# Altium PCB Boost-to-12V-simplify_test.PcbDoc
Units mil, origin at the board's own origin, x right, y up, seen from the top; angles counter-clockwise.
Board outline 618 x 524 mil, 2 copper layers (Top Layer, Bottom Layer); 13 components, 7 nets, 29 pads, 14 vias.
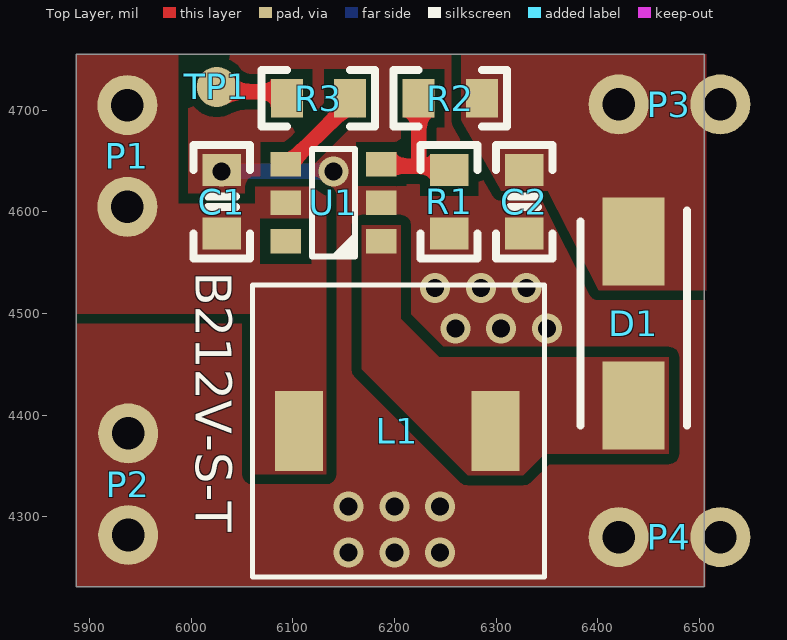
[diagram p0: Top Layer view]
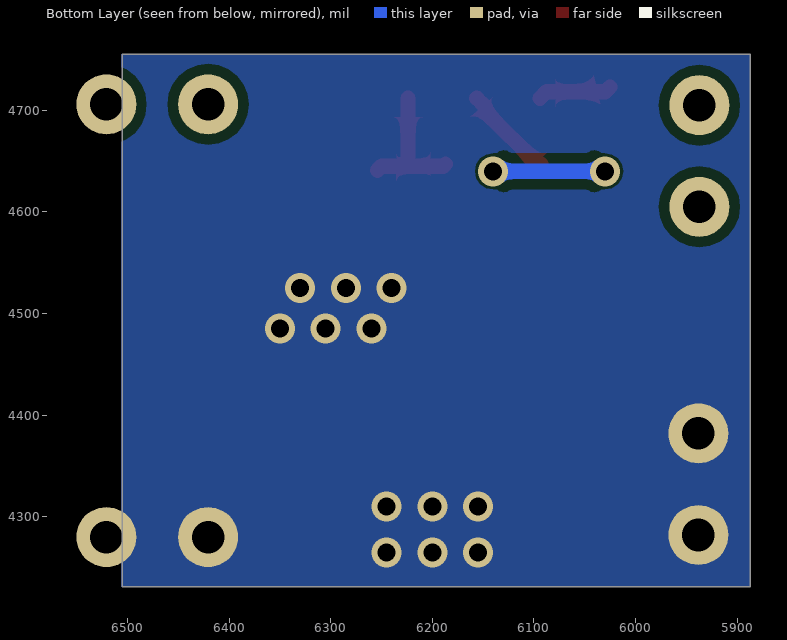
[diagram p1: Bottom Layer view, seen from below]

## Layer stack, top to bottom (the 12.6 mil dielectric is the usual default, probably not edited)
Top Solder: solder mask 0.4, Solder Resist, Dk 3.5
Top Layer: signal copper 1.4
Dielectric 1: dielectric 12.6, FR-4, Dk 4.8
Bottom Layer: signal copper 1.4
Bottom Solder: solder mask 0.4, Solder Resist, Dk 3.5

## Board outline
5887,4231 5887,4755 6505,4755 6505,4231

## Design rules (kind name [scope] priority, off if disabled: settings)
Clearance [All] p1: gap=10 ignorepadtopadclearanceinfootprint=FALSE except(0: Arc-Hole Track-Hole SMDPad-Hole THPad-Hole Via-Hole Fill-Hole Poly-Hole Region-Hole Text-Hole)
PlaneConnect [All] p1: planeconnectstyle=Direct reliefexpansion=20 reliefentries=4 reliefconductorwidth=10 reliefairgap=10
PolygonConnect [All] p1: connectstyle=Direct reliefconductorwidth=10 reliefentries=4 polygonreliefangle="90 Angle" airgapwidth=10
RoutingVias [All] p1: holewidth=17.72 width=29.53 viastyle="Through Hole" minholewidth=17.72 minwidth=29.53 maxholewidth=17.72 maxwidth=29.53
SolderMaskExpansion [All] p1: expansion=4 istentingtop=FALSE
Width [All] p1: maxlimit=100 minlimit=10 preferedwidth=15
29 further rules are at their usual default settings.

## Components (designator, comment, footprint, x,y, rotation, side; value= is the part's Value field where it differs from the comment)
C1 "22uF/25V" CAP-0603 6030.05,4610 r270 top
C2 "22uF/25V" CAP-0603 6327.77,4610 r90 top
D1 "SS34" DO-214AC_SMA 6435.46,4490 r270 top
L1 "4.7uH/4A" SMD_7.3x7.3x4.2mm 6185.49,4369.78 r0 top
P1 "HDR1x2_2.54" HDR1X2_2.54_180 5937.11,4705 r0 top
P2 "HDR1x2_2.54" HDR1X2_2.54_180 5938,4282 r180 top
P3 "HDR1x2_2.54" HDR1X2_2.54_180 6420.72,4705.85 r90 top
P4 "HDR1x2_2.54" HDR1X2_2.54_180 6420.72,4280 r90 top
R1 "594R" R-0603 6253.88,4610 r90 top
R2 "10k" R-0603 6255,4711.88 r0 top
R3 "100k" R-0603 6125.12,4711.88 r0 top
TP1 "TestPoint" TestPoint 6025,4723 r90 top
U1 "SX1308" SOT-23-6 6140,4609.06 r0 top

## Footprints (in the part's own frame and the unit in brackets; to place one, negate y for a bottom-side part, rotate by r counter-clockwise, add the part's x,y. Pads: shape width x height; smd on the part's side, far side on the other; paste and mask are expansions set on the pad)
CAP-0603 [mm]
  rect 0.8x0.96 smd: 1(-0.79,0) 2(0.79,0)
  silkscreen extent -1.42,-0.71 1.42,0.71, body extent -0.76,-0.39 0.76,0.39, height 0.9
DO-214AC_SMA [mm]
  rect 2.2x1.55 smd: 1(2.05,0) 2(-2.05,0)
  silkscreen extent -2.83,-1.33 2.55,1.33, body extent -2.55,-1.33 2.55,1.33, height 2.29
HDR1X2_2.54_180 [mm]
  round 1.5 hole 0.813: 1(0,0) 2(0,-2.54)
  body extent -1.25,-3.81 1.25,1.27, height 8.2
R-0603 [mm]
  rect 0.8x0.96 smd: 1(-0.79,0) 2(0.79,0)
  silkscreen extent -1.42,-0.71 1.42,0.71, body extent -0.76,-0.38 0.76,0.38, height 0.41
SMD_7.3x7.3x4.2mm [mm]
  rect 1.2x2 smd: 1(-2.02,0.37) 2(2.9,0.37)
  silkscreen extent -3.18,-3.28 4.12,4.02, body extent -3.18,-3.28 4.1,4, height 3
SOT-23-6 [mil]
  rect 30x24 smd: 1(47,-38) 2(47,0) 3(47,38) 4(-47,38) 5(-47,0) 6(-47,-38)
  silkscreen extent -21,-53 21,53, body extent -55,-57 55,57, height 57
TestPoint [mm]
  round 1 smd: 1(0,0)

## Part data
C1 C2: library part CAP, "X7R", Package=0402, SuppliersPartNumber=C52923
D1: library part DIODE, "肖特基二极管", Package=SMA(DO-214AC), SuppliersPartNumber=C22452
L1: library part INDUCTOR, "电感", Package=0402, SuppliersPartNumber=C32041
P1 P2 P3 P4: "Header"
R1 R2 R3: library part RES, "贴片电阻", Package=0805, SuppliersPartNumber=C17798
TP1: "测试点"
U1: "集成升压芯片", Manufacturer_Name="Shenzhen Suosemi Tech"

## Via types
v1: diameter 29.53, hole 17.72, Top Layer to Bottom Layer, 14 vias

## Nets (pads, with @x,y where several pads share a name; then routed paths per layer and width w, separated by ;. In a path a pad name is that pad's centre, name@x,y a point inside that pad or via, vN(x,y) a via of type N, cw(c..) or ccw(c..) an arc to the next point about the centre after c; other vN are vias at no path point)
5V: C1.2 L1.1 P1.1 P1.2 U1.5
12V: C2.2 D1.2 P3.1 P3.2 R2.2
GND: C1.1 C2.1 P2.1 P2.2 P4.1 P4.2 R1.1 U1.2 | length 111.2
  Top Layer w15: v1(6030,4640) 6030,4641.1 C1.1
  Bottom Layer w15: v1(6030,4640) v1(6140,4640)
  other v1: 6155,4265 6200,4265 6245,4265 6155,4310 6200,4310 6245,4310 6260,4485 6305,4485 6350,4485 6240,4525 6285,4525 6330,4525
NetD1_1: D1.1 L1.2 U1.1
NetR1_2: R1.2 R2.1 U1.3 | length 138
  Top Layer w15: U1.3 6189.06,4645 6219.52,4645 ; R2.1 6223.9,4649.37 6219.52,4645 ; R1.2 6249.99,4645 6219.52,4645
NetR3_1: R3.1 TP1.1 | length 73.6
  Top Layer w15: TP1.1 6029.66,4718.34 6087.56,4718.34 R3.1
NetR3_2: R3.2 U1.4 | length 92.8
  Top Layer w15: U1.4 6096,4647.06 6147.97,4699.03 6147.97,4703.64 R3.2
pads on no net: U1.6

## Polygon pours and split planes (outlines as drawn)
GND on Top Layer "NONET_L01_P-001" (solid, remove dead copper, pour order 5): 5887,4231 6506,4231 6506,4755 5887,4755
12V on Top Layer "NONET_L01_P-001" (solid, pour order 3): 6401,4523 6507,4523 6507,4755 6266,4755 6266,4690 6305,4621 6351,4621
NetD1_1 on Top Layer "NONET_L01_P-001" (solid, pour order 1): 6168,4587 6168,4445 6272,4341 6327,4341 6348,4362 6470,4362 6470,4457 6244,4457 6206,4495 6206,4587
5V on Top Layer "NONET_L01_P-001" (solid, pour order 0): 5887,4755 5887,4500 6060,4500 6060,4342 6133,4342 6133,4625 6063,4625 6063,4608 5987,4608 5987,4755
GND on Bottom Layer "NONET_L01_P-001" (solid, pour order 7): 5887,4231 6506,4231 6506,4755 5887,4755
GND on Top Solder "NONET_L01_P-001" (solid): 5988,4232 5888,4232 5888,4471 5988,4471
GND on Top Solder "NONET_L01_P-001" (solid): 6353,4230 6353,4351 6509,4351 6509,4230
12V on Top Solder "NONET_L01_P-001" (solid): 6370.72,4656 6370.72,4755.85 6509,4755.85 6509,4656
5V on Top Solder "NONET_L01_P-001" (solid): 5987.11,4521 5887.11,4521 5887.11,4755 5987.11,4755
5V on Bottom Solder "NONET_L01_P-001" (solid): 5987.11,4521 5887.11,4521 5887.11,4755 5987.11,4755
12V on Bottom Solder "NONET_L01_P-001" (solid): 6370.72,4656 6370.72,4755.85 6509,4755.85 6509,4656
GND on Bottom Solder "NONET_L01_P-001" (solid): 6353,4230 6353,4351 6509,4351 6509,4230
GND on Bottom Solder "NONET_L01_P-001" (solid): 5988,4232 5888,4232 5888,4471 5988,4471

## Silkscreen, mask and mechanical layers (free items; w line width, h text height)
Top Overlay:
  text "B212V-S-T" at 6004.29,4541.09 h35.43 r270
Mechanical 1:
  the board outline again, w12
